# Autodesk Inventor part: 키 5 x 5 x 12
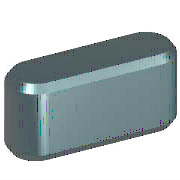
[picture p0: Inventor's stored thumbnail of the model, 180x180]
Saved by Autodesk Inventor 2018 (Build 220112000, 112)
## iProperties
IsCustomPart: 1
Created: 2012-02
Part Number: 키 5 x 5 x 12
Material: 강철, 연강
Description: 키 및 해당 키홈
Document SubType Name: Modeling
Standard: KS B 1311
Designer: mduedu
Standards Organization: KS
Language: ko-KR
Size Designation: 5 x 5 x 12
Categories: <MemberInstance><Categories><Category DisplayName="샤프트 부품" InternalName="7f7aeb1f-a693-4053-b835-cee3144e0d98" Mnemonic="SHFT"><Category DisplayName="키" Interna
Density: 7.86 g/cm^3
Mass: 2.11085 g
Surface Area: 2.43471 cm^2
Volume: 0.268556 cm^3
Appearance: 노란색
Author: mduedu
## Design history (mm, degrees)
workplane "Work Plane1"
workplane "Work Plane2"
sketch "스케치1"
  geometry: L1 (2.5, 2.5)-(9.5, 2.5); L2 (9.5, -2.5)-(2.5, -2.5); L3 (0, 9.4)-(0, -7.4) reference; L4 (-5, 0)-(30, 0) reference; L5 (12, 0)-(12, 7); A1 r 2.5 centre (2.5, 0) between (2.5, 2.5) and (2.5, -2.5); A2 r 2.5 centre (9.5, 0) between (9.5, -2.5) and (9.5, 2.5)
  constraints: 6 end point, 5 point on circle, 4 tangent, 3 point on line, 2 centre point, 1 horizontal, 1 parallel, 1 perpendicular
  dimensions: "d0" = 2.5 radius of A1 (= 0.5 x PB); "d13" = 2.5 radius of A2 (= 0.5 x PB); "d14" = 12 distance between parallel lines of L5 L3 (= NLG)
extrude "본체1" new body sketch "스케치1" taper "d3" = 0 deg; stored distance "d4" = 10
workplane "Work Plane3"
body "Solid1"
chamfer "모따기1" distance "d8" = 0.4 (= PHH); stored, may be unused: second distance "d9" = 0.4 (= PHH), angle "d15" = 45 deg
other parameters: "d1" = -3 (= -PNT), "d2" = 2 (= PH - PNT), "NLG" = 12 [user parameter; used in 3 equation terms], "PB" = 5 [user parameter; used in 2 equation terms], "PNT" = 3 [user parameter; used in 2 equation terms], "PH" = 5 [user parameter; used in 1 equation term], "PHH" = 0.4 [user parameter; used in 2 equation terms], "d10" = 0, "d16" = 0, "d17" = 0, "d18" = 0, "WDMIN" = 12 [user parameter], "PLB2" = 12 (= NLG) [user parameter], "WDMAX" = 17 [user parameter], "PLB1" = 12 (= NLG) [user parameter], "RR" = 0.16 [user parameter], "PUEB" = 2.3 [user parameter]
